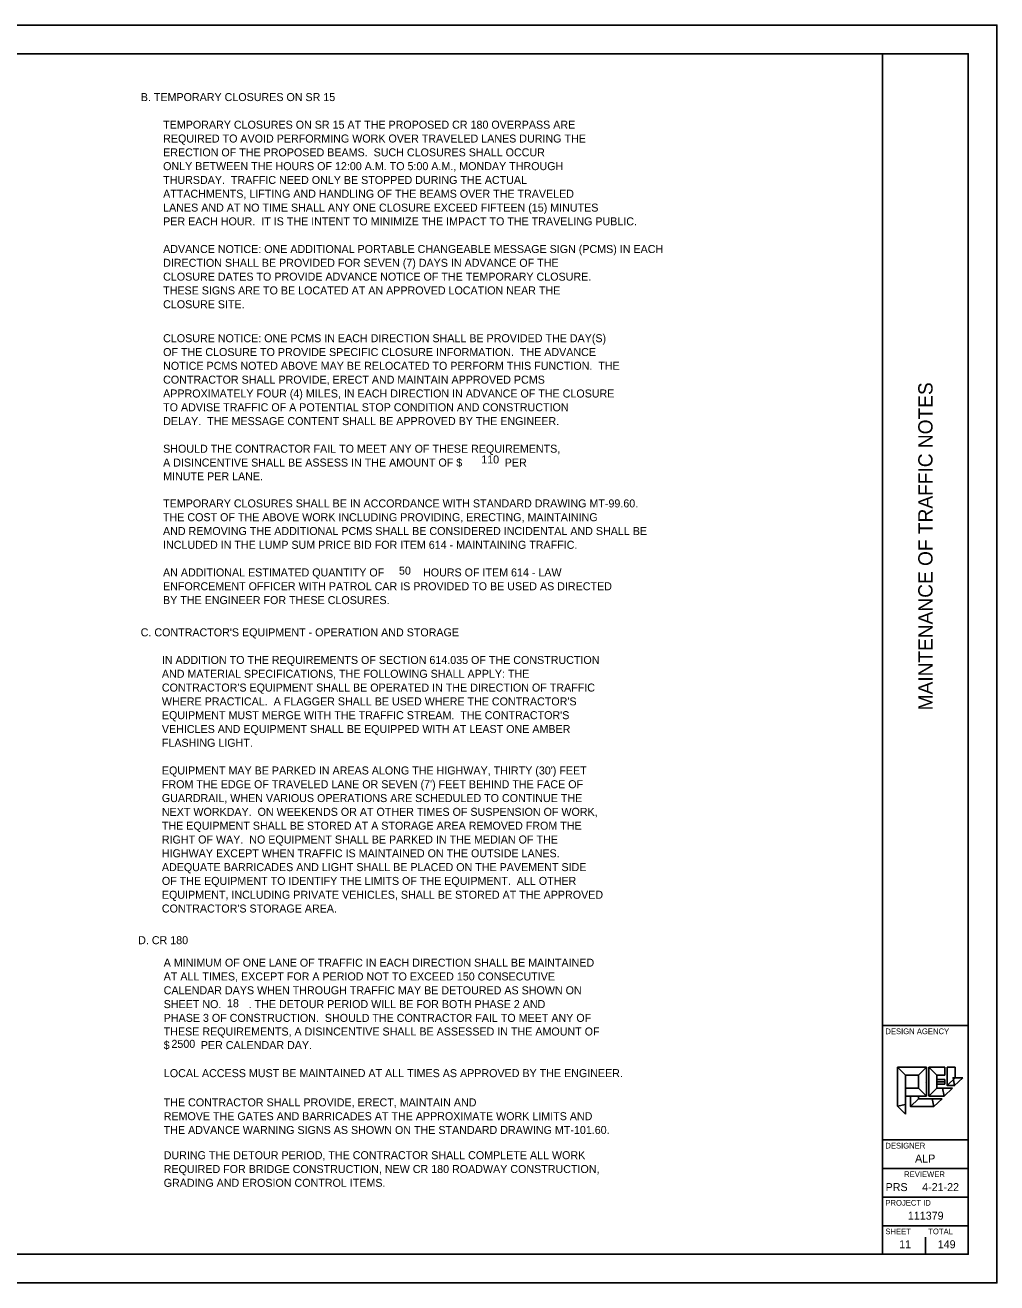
# Model space of a CAD drawing. Extents: x 0 to 34, y 36.8 to 58.8.
# Drawn here: x 17 to 34, y 36.85 to 58.85 of the extents above; entities that cross this region are included whole.
import ezdxf

# ---------------------------------------------------------------- set-up
doc = ezdxf.new("R2010")
doc.units = 0
for name, color, linetype in [('Default', 7, 'Continuous'), ('SH_Border', 7, 'Continuous'), ('SH_Cut_Line', 7, 'Continuous'), ('SH_Data', 7, 'Continuous')]:
    doc.layers.add(name, color=color, linetype=linetype)

msp = doc.modelspace()

# ---------------------------------------------------------------- linework, layer by layer
at = {"layer": 'Default'}
msp.add_line((32.95, 40.366), (33.087, 40.366), dxfattribs=at)
msp.add_line((32.95, 40.366), (33.087, 40.366), dxfattribs=at)
for points in [[(32.264, 39.94), (32.264, 40.617), (32.401, 40.48), (32.401, 39.968)], [(32.264, 40.617), (32.767, 40.617), (32.63, 40.48), (32.401, 40.48)], [(32.264, 39.94), (32.264, 40.617), (32.401, 40.48), (32.401, 39.968)], [(32.264, 40.617), (32.767, 40.617), (32.63, 40.48), (32.401, 40.48)], [(32.767, 40.617), (32.767, 40.115), (32.63, 40.251), (32.63, 40.48)], [(32.767, 40.617), (32.767, 40.115), (32.63, 40.251), (32.63, 40.48)], [(32.812, 40.115), (32.812, 40.617), (32.95, 40.48), (32.95, 40.251)], [(32.812, 40.617), (33.087, 40.617), (33.087, 40.48), (32.95, 40.48)], [(32.812, 40.115), (32.812, 40.617), (32.95, 40.48), (32.95, 40.251)], [(32.812, 40.617), (33.087, 40.617), (33.087, 40.48), (32.95, 40.48)], [(33.132, 40.297), (33.132, 40.617), (33.27, 40.617), (33.27, 40.435)], [(33.132, 40.297), (33.132, 40.617), (33.27, 40.617), (33.27, 40.435)], [(33.087, 40.407), (33.087, 40.324), (32.951, 40.324), (32.951, 40.407)], [(33.087, 40.407), (33.087, 40.324), (32.951, 40.324), (32.951, 40.407)], [(33.261, 40.297), (33.132, 40.297), (33.27, 40.435), (33.233, 40.435)], [(33.261, 40.297), (33.132, 40.297), (33.27, 40.435), (33.233, 40.435)], [(33.407, 40.435), (33.261, 40.297), (33.233, 40.435)], [(33.407, 40.435), (33.261, 40.297), (33.233, 40.435)], [(32.767, 40.115), (32.401, 40.115), (32.401, 40.251), (32.63, 40.251)], [(32.767, 40.115), (32.401, 40.115), (32.401, 40.251), (32.63, 40.251)], [(32.492, 39.931), (32.492, 40.115), (32.63, 40.115), (32.63, 40.068)], [(32.492, 39.931), (32.492, 40.115), (32.63, 40.115), (32.63, 40.068)], [(32.895, 39.931), (32.492, 39.931), (32.63, 40.068), (32.867, 40.068)], [(32.895, 39.931), (32.492, 39.931), (32.63, 40.068), (32.867, 40.068)], [(33.078, 40.115), (32.812, 40.115), (32.95, 40.251), (33.05, 40.251)], [(33.078, 40.115), (32.812, 40.115), (32.95, 40.251), (33.05, 40.251)], [(33.041, 40.068), (32.895, 39.931), (32.867, 40.068)], [(33.041, 40.068), (32.895, 39.931), (32.867, 40.068)], [(33.224, 40.251), (33.078, 40.115), (33.05, 40.251)], [(33.224, 40.251), (33.078, 40.115), (33.05, 40.251)], [(32.401, 39.795), (32.264, 39.94), (32.401, 39.968)], [(32.401, 39.795), (32.264, 39.94), (32.401, 39.968)]]:
    msp.add_lwpolyline(points, close=True, dxfattribs=at)
at = {"layer": 'SH_Border'}
for p, q in [((32, 37.347), (32, 58.347)), ((32, 41.347), (33.5, 41.347)), ((32, 39.347), (33.5, 39.347)), ((32, 38.847), (33.5, 38.847)), ((32, 38.347), (33.5, 38.347)), ((32, 37.847), (33.5, 37.847))]:
    msp.add_line(p, q, dxfattribs=at)
msp.add_lwpolyline([(1.5, 58.347), (33.5, 58.347), (33.5, 37.347), (1.5, 37.347)], close=True, dxfattribs=at)
at = {"layer": 'SH_Cut_Line'}
msp.add_lwpolyline([(0, 36.847), (34, 36.847), (34, 58.847), (0, 58.847)], close=True, dxfattribs=at)
at = {"layer": 'SH_Data'}
for p, q in [((32.75, 40.347), (32.75, 40.347)), ((32.75, 37.347), (32.75, 37.647))]:
    msp.add_line(p, q, dxfattribs=at)

# ---------------------------------------------------------------- texts
at = {"layer": 'Default'}
for s, p in [('B. TEMPORARY CLOSURES ON SR 15', (19.023, 57.519)), ('TEMPORARY CLOSURES ON SR 15 AT THE PROPOSED CR 180 OVERPASS ARE', (19.414, 57.036)), ('REQUIRED TO AVOID PERFORMING WORK OVER TRAVELED LANES DURING THE', (19.414, 56.794)), ('ERECTION OF THE PROPOSED BEAMS.  SUCH CLOSURES SHALL OCCUR', (19.414, 56.552)), ('ONLY BETWEEN THE HOURS OF 12:00 A.M. TO 5:00 A.M., MONDAY THROUGH', (19.414, 56.311)), ('THURSDAY.  TRAFFIC NEED ONLY BE STOPPED DURING THE ACTUAL', (19.414, 56.069)), ('ATTACHMENTS, LIFTING AND HANDLING OF THE BEAMS OVER THE TRAVELED', (19.414, 55.828)), ('LANES AND AT NO TIME SHALL ANY ONE CLOSURE EXCEED FIFTEEN (15) MINUTES', (19.414, 55.586)), ('PER EACH HOUR.  IT IS THE INTENT TO MINIMIZE THE IMPACT TO THE TRAVELING PUBLIC.', (19.414, 55.345)), ('ADVANCE NOTICE: ONE ADDITIONAL PORTABLE CHANGEABLE MESSAGE SIGN (PCMS) IN EACH', (19.414, 54.861)), ('DIRECTION SHALL BE PROVIDED FOR SEVEN (7) DAYS IN ADVANCE OF THE', (19.414, 54.62)), ('CLOSURE DATES TO PROVIDE ADVANCE NOTICE OF THE TEMPORARY CLOSURE. ', (19.414, 54.378)), ('THESE SIGNS ARE TO BE LOCATED AT AN APPROVED LOCATION NEAR THE', (19.414, 54.137)), ('CLOSURE SITE.', (19.414, 53.895)), ('CLOSURE NOTICE: ONE PCMS IN EACH DIRECTION SHALL BE PROVIDED THE DAY(S)', (19.414, 53.301)), ('OF THE CLOSURE TO PROVIDE SPECIFIC CLOSURE INFORMATION.  THE ADVANCE', (19.414, 53.059)), ('NOTICE PCMS NOTED ABOVE MAY BE RELOCATED TO PERFORM THIS FUNCTION.  THE', (19.414, 52.818)), ('CONTRACTOR SHALL PROVIDE, ERECT AND MAINTAIN APPROVED PCMS', (19.414, 52.576)), ('APPROXIMATELY FOUR (4) MILES, IN EACH DIRECTION IN ADVANCE OF THE CLOSURE', (19.414, 52.334)), ('TO ADVISE TRAFFIC OF A POTENTIAL STOP CONDITION AND CONSTRUCTION', (19.414, 52.093)), ('DELAY.  THE MESSAGE CONTENT SHALL BE APPROVED BY THE ENGINEER.', (19.414, 51.851)), ('SHOULD THE CONTRACTOR FAIL TO MEET ANY OF THESE REQUIREMENTS,', (19.414, 51.368)), ('A DISINCENTIVE SHALL BE ASSESS IN THE AMOUNT OF $ ', (19.414, 51.126)), ('110', (24.979, 51.18)), ('   PER', (25.234, 51.126)), ('MINUTE PER LANE.', (19.414, 50.885)), ('TEMPORARY CLOSURES SHALL BE IN ACCORDANCE WITH STANDARD DRAWING MT-99.60.', (19.414, 50.411)), ('THE COST OF THE ABOVE WORK INCLUDING PROVIDING, ERECTING, MAINTAINING', (19.412, 50.17)), ('AND REMOVING THE ADDITIONAL PCMS SHALL BE CONSIDERED INCIDENTAL AND SHALL BE', (19.412, 49.928)), ('INCLUDED IN THE LUMP SUM PRICE BID FOR ITEM 614 - MAINTAINING TRAFFIC.', (19.412, 49.687)), ('AN ADDITIONAL ESTIMATED QUANTITY OF ', (19.412, 49.204)), ('50', (23.54, 49.235)), ('  HOURS OF ITEM 614 - LAW', (23.857, 49.204)), ('ENFORCEMENT OFFICER WITH PATROL CAR IS PROVIDED TO BE USED AS DIRECTED', (19.412, 48.962)), ('BY THE ENGINEER FOR THESE CLOSURES.', (19.412, 48.72)), ("C. CONTRACTOR'S EQUIPMENT - OPERATION AND STORAGE", (19.021, 48.156)), ('IN ADDITION TO THE REQUIREMENTS OF SECTION 614.035 OF THE CONSTRUCTION', (19.392, 47.673)), ('AND MATERIAL SPECIFICATIONS, THE FOLLOWING SHALL APPLY: THE', (19.392, 47.431)), ("CONTRACTOR'S EQUIPMENT SHALL BE OPERATED IN THE DIRECTION OF TRAFFIC", (19.392, 47.19)), ("WHERE PRACTICAL.  A FLAGGER SHALL BE USED WHERE THE CONTRACTOR'S", (19.392, 46.948)), ("EQUIPMENT MUST MERGE WITH THE TRAFFIC STREAM.  THE CONTRACTOR'S", (19.392, 46.707)), ('VEHICLES AND EQUIPMENT SHALL BE EQUIPPED WITH AT LEAST ONE AMBER', (19.392, 46.465)), ('FLASHING LIGHT.', (19.392, 46.224)), ("EQUIPMENT MAY BE PARKED IN AREAS ALONG THE HIGHWAY, THIRTY (30') FEET", (19.392, 45.74)), ("FROM THE EDGE OF TRAVELED LANE OR SEVEN (7') FEET BEHIND THE FACE OF", (19.392, 45.499)), ('GUARDRAIL, WHEN VARIOUS OPERATIONS ARE SCHEDULED TO CONTINUE THE', (19.392, 45.257)), ('NEXT WORKDAY.  ON WEEKENDS OR AT OTHER TIMES OF SUSPENSION OF WORK,', (19.392, 45.016)), ('THE EQUIPMENT SHALL BE STORED AT A STORAGE AREA REMOVED FROM THE', (19.392, 44.774)), ('RIGHT OF WAY.  NO EQUIPMENT SHALL BE PARKED IN THE MEDIAN OF THE', (19.392, 44.532)), ('HIGHWAY EXCEPT WHEN TRAFFIC IS MAINTAINED ON THE OUTSIDE LANES. ', (19.392, 44.291)), ('ADEQUATE BARRICADES AND LIGHT SHALL BE PLACED ON THE PAVEMENT SIDE', (19.392, 44.049)), ('OF THE EQUIPMENT TO IDENTIFY THE LIMITS OF THE EQUIPMENT.  ALL OTHER', (19.392, 43.808)), ('EQUIPMENT, INCLUDING PRIVATE VEHICLES, SHALL BE STORED AT THE APPROVED ', (19.392, 43.566)), ("CONTRACTOR'S STORAGE AREA.", (19.392, 43.325)), ('D. CR 180', (18.977, 42.771)), ('A MINIMUM OF ONE LANE OF TRAFFIC IN EACH DIRECTION SHALL BE MAINTAINED', (19.424, 42.378)), ('AT ALL TIMES, EXCEPT FOR A PERIOD NOT TO EXCEED 150 CONSECUTIVE', (19.424, 42.137)), ('CALENDAR DAYS WHEN THROUGH TRAFFIC MAY BE DETOURED AS SHOWN ON', (19.424, 41.895)), ('18', (20.531, 41.669)), ('SHEET NO. ', (19.424, 41.653)), (' . THE DETOUR PERIOD WILL BE FOR BOTH PHASE 2 AND ', (20.858, 41.653)), ('PHASE 3 OF CONSTRUCTION.  SHOULD THE CONTRACTOR FAIL TO MEET ANY OF ', (19.424, 41.412)), ('THESE REQUIREMENTS, A DISINCENTIVE SHALL BE ASSESSED IN THE AMOUNT OF ', (19.424, 41.174)), ('$ ', (19.424, 40.936)), ('2500', (19.559, 40.958)), (' PER CALENDAR DAY.', (20.021, 40.936)), ('LOCAL ACCESS MUST BE MAINTAINED AT ALL TIMES AS APPROVED BY THE ENGINEER.', (19.427, 40.445)), ('THE CONTRACTOR SHALL PROVIDE, ERECT, MAINTAIN AND', (19.424, 39.934)), ('REMOVE THE GATES AND BARRICADES AT THE APPROXIMATE WORK LIMITS AND', (19.424, 39.692)), ('THE ADVANCE WARNING SIGNS AS SHOWN ON THE STANDARD DRAWING MT-101.60.', (19.424, 39.451)), ('DURING THE DETOUR PERIOD, THE CONTRACTOR SHALL COMPLETE ALL WORK', (19.424, 39.01)), ('REQUIRED FOR BRIDGE CONSTRUCTION, NEW CR 180 ROADWAY CONSTRUCTION,', (19.424, 38.768)), ('GRADING AND EROSION CONTROL ITEMS.', (19.424, 38.527))]:
    msp.add_text(s, height=0.14, dxfattribs=at).set_placement(p)
at = {"layer": 'SH_Data'}
msp.add_text('MAINTENANCE OF TRAFFIC NOTES', height=0.25, rotation=90, dxfattribs=at).set_placement((32.875, 46.861))
for s, height, p in [('DESIGN AGENCY', 0.1, (32.05, 41.197)), ('DESIGNER', 0.1, (32.05, 39.197)), ('ALP', 0.14, (32.569, 38.952)), ('REVIEWER', 0.1, (32.378, 38.697)), ('PRS', 0.14, (32.054, 38.452)), ('4-21-22', 0.14, (32.693, 38.452)), ('PROJECT ID', 0.1, (32.05, 38.197)), ('111379', 0.14, (32.443, 37.952)), ('SHEET', 0.1, (32.05, 37.697)), ('TOTAL', 0.1, (32.8, 37.697)), ('11', 0.14, (32.291, 37.452)), ('149', 0.14, (32.966, 37.452))]:
    msp.add_text(s, height=height, dxfattribs=at).set_placement(p)

doc.saveas('drawing.dxf')
